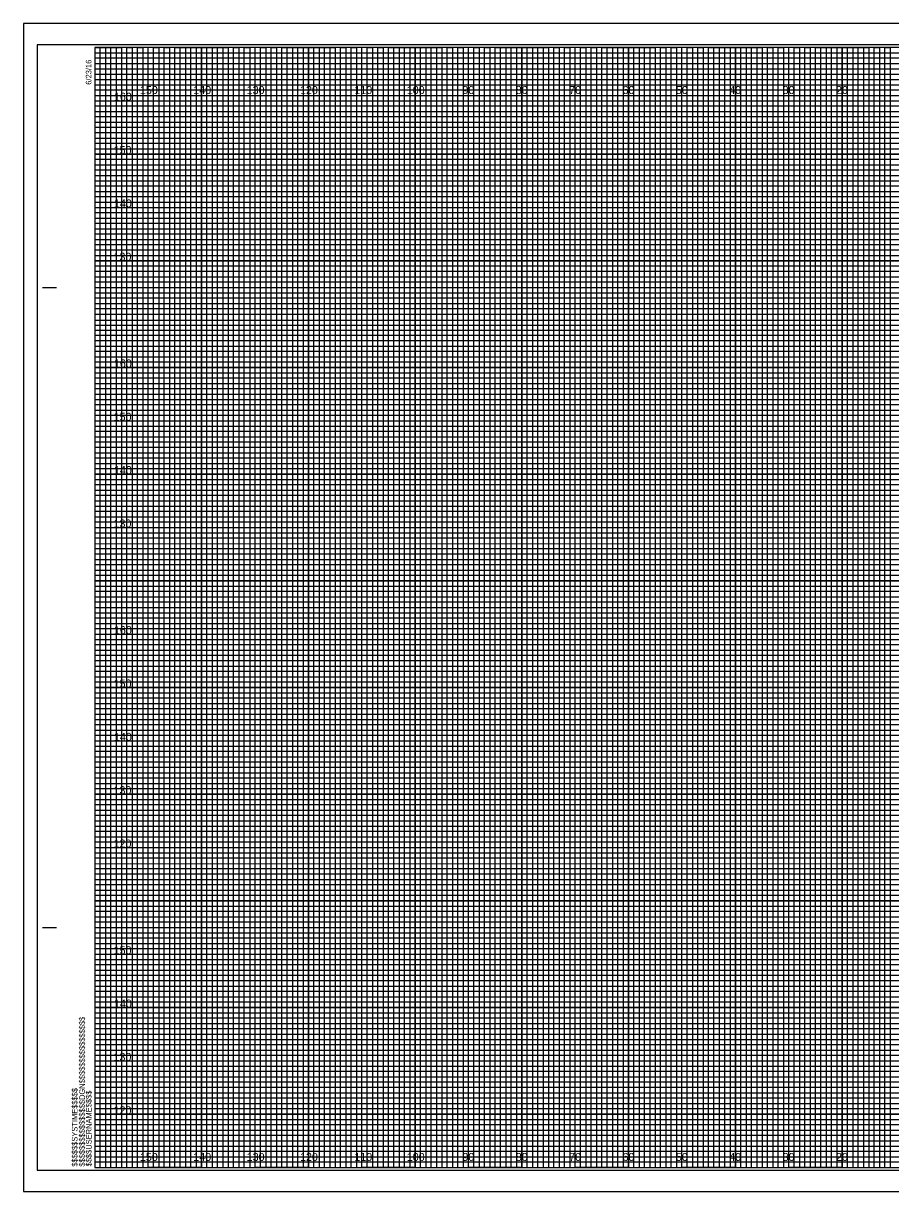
# Model space of a CAD drawing. Extents: x -13 to 323, y -5 to 874.
# Drawn here: x -13.4 to 149.1, y 435.5 to 654.5 of the extents above; entities that cross this region are included whole.
import ezdxf

# ---------------------------------------------------------------- set-up
doc = ezdxf.new("R2010")
doc.units = 0
for name, color, linetype in [('Exist Cross Section Cell', 7, 'Continuous'), ('Exist XS Center Line Elevation Label', 7, 'Continuous'), ('Exist XS Ground Line', 7, 'Continuous'), ('Prop CMT Pvmt Course 1', 7, 'Continuous'), ('Prop CMT Pvmt Course 3', 7, 'Continuous'), ('Prop CMT Pvmt Surface', 7, 'Continuous'), ('Prop CMT Pvmt Surface Shoulder', 7, 'Continuous'), ('Prop CMT Shld Paved Course 1', 7, 'Continuous'), ('Prop CMT Shld Paved Course 2', 7, 'Continuous'), ('Prop CMT Shld Paved Course 3', 7, 'Continuous'), ('Prop CMT Subgrade Earthwork', 7, 'Continuous')]:
    doc.layers.add(name, color=color, linetype=linetype)

msp = doc.modelspace()

# ---------------------------------------------------------------- linework, layer by layer
at = {"layer": 'Exist XS Center Line Elevation Label'}
for points in [[(0, 650), (5, 650), (5, 440), (15, 440), (15, 650), (25, 650), (25, 440), (35, 440), (35, 650), (45, 650), (45, 440), (55, 440), (55, 650), (65, 650), (65, 440), (75, 440), (75, 650), (85, 650), (85, 440), (95, 440), (95, 650), (105, 650), (105, 440), (115, 440), (115, 650), (125, 650), (125, 440), (135, 440), (135, 650), (145, 650), (145, 440), (155, 440)], [(0, 645), (275, 645)], [(0, 625), (320, 625), (320, 635), (0, 635)], [(0, 605), (320, 605), (320, 615), (0, 615)], [(0, 585), (320, 585), (320, 595), (0, 595)], [(0, 565), (320, 565), (320, 575), (0, 575)], [(0, 545), (320, 545), (320, 555), (0, 555)], [(0, 525), (320, 525), (320, 535), (0, 535)], [(0, 505), (320, 505), (320, 515), (0, 515)], [(0, 485), (320, 485), (320, 495), (0, 495)], [(0, 465), (320, 465), (320, 475), (0, 475)], [(0, 445), (320, 445), (320, 455), (0, 455)]]:
    msp.add_lwpolyline(points, dxfattribs=at)
at = {"layer": 'Exist XS Ground Line'}
for p, q in [((10, 650), (0, 650)), ((10, 440), (10, 650)), ((30, 650), (20, 650)), ((20, 650), (20, 440)), ((30, 440), (30, 650)), ((50, 650), (40, 650)), ((40, 650), (40, 440)), ((50, 440), (50, 650)), ((70, 650), (60, 650)), ((60, 650), (60, 440)), ((70, 440), (70, 650)), ((90, 650), (80, 650)), ((80, 650), (80, 440)), ((90, 440), (90, 650)), ((110, 650), (100, 650)), ((100, 650), (100, 440)), ((110, 440), (110, 650)), ((130, 650), (120, 650)), ((120, 650), (120, 440)), ((130, 440), (130, 650)), ((150, 650), (140, 650)), ((140, 650), (140, 440)), ((20, 440), (10, 440)), ((40, 440), (30, 440)), ((60, 440), (50, 440)), ((80, 440), (70, 440)), ((100, 440), (90, 440)), ((120, 440), (110, 440)), ((140, 440), (130, 440))]:
    msp.add_line(p, q, dxfattribs=at)
for points in [[(0, 640), (320, 640), (320, 630), (0, 630)], [(0, 620), (320, 620), (320, 610), (0, 610)], [(0, 600), (320, 600), (320, 590), (0, 590)], [(0, 580), (320, 580), (320, 570), (0, 570)], [(0, 560), (320, 560), (320, 550), (0, 550)], [(0, 540), (320, 540), (320, 530), (0, 530)], [(0, 520), (320, 520), (320, 510), (0, 510)], [(0, 500), (320, 500), (320, 490), (0, 490)], [(0, 480), (320, 480), (320, 470), (0, 470)], [(0, 460), (320, 460), (320, 450), (0, 450)]]:
    msp.add_lwpolyline(points, dxfattribs=at)
at = {"layer": 'Prop CMT Pvmt Course 3'}
msp.add_lwpolyline([(-13.4, 435.5), (323.3, 435.5), (323.3, 654.5), (-13.4, 654.5)], close=True, dxfattribs=at)
at = {"layer": 'Prop CMT Pvmt Surface'}
for p, q in [((10, 440), (10, 650)), ((20, 440), (20, 650)), ((30, 440), (30, 650)), ((40, 440), (40, 650)), ((50, 440), (50, 650)), ((60, 440), (60, 650)), ((70, 440), (70, 650)), ((80, 440), (80, 650)), ((90, 440), (90, 650)), ((100, 440), (100, 650)), ((110, 440), (110, 650)), ((120, 440), (120, 650)), ((130, 440), (130, 650)), ((140, 440), (140, 650)), ((0, 640), (320, 640)), ((0, 630), (320, 630)), ((0, 620), (320, 620)), ((0, 610), (320, 610)), ((0, 600), (320, 600)), ((0, 590), (320, 590)), ((0, 580), (320, 580)), ((0, 570), (320, 570)), ((0, 560), (320, 560)), ((0, 550), (320, 550)), ((0, 540), (320, 540)), ((0, 530), (320, 530)), ((0, 520), (320, 520)), ((0, 510), (320, 510)), ((0, 500), (320, 500)), ((0, 490), (320, 490)), ((0, 480), (320, 480)), ((0, 470), (320, 470)), ((0, 460), (320, 460)), ((0, 450), (320, 450))]:
    msp.add_line(p, q, dxfattribs=at)
at = {"layer": 'Prop CMT Pvmt Surface Shoulder'}
for p, q in [((323.3, 654.5), (-13.4, 654.5)), ((-13.4, 654.5), (-13.4, 435.5)), ((-13.4, 435.5), (323.3, 435.5))]:
    msp.add_line(p, q, dxfattribs=at)
at = {"layer": 'Prop CMT Shld Paved Course 1'}
for p, q in [((0, 649), (260, 649)), ((260, 647.98), (0, 647.98)), ((0, 647.98), (0, 647)), ((0, 647), (260, 647)), ((260, 645.89), (0, 645.89)), ((0, 645.89), (0, 644)), ((0, 644), (320, 644))]:
    msp.add_line(p, q, dxfattribs=at)
for points in [[(0, 643), (270, 643), (320, 643), (320, 642), (0, 642)], [(0, 641), (320, 641), (320, 639), (0, 639)], [(0, 638), (320, 638), (320, 637), (0, 636.98)], [(0, 636), (320, 636), (320, 634), (0, 634)], [(0, 633), (320, 633), (320, 632), (0, 632)], [(0, 631), (320, 631), (320, 629), (0, 629)], [(0, 628), (320, 628), (320, 627), (0, 627)], [(0, 626), (320, 626), (320, 624), (0, 624)], [(0, 623), (320, 623), (320, 622), (0, 622)], [(0, 621), (320, 621), (320, 619), (0, 619)], [(0, 618), (320, 618), (320, 617), (0, 617)], [(0, 616), (320, 616), (320, 613.95), (320, 613), (320, 612), (0, 612)], [(0, 614), (320, 614), (320, 613), (0, 613)], [(0, 611), (320, 611), (320, 609), (0, 609.03)], [(0, 609.03), (320, 609), (320, 608), (0, 608)], [(0, 607), (320, 607), (320, 606), (0, 606)], [(0, 604), (320, 604), (320, 603), (0, 603)], [(0, 602), (320, 602), (320, 601), (0, 601)], [(-0.07, 598.89), (320, 598.89), (320, 597.88), (-0.07, 597.88)], [(0, 597), (320, 597), (320, 596), (0, 596)], [(0, 594), (320, 594), (320, 593), (0, 593)], [(0, 592), (320, 592), (320, 591), (0, 591)], [(0, 589), (320, 589), (320, 588), (0, 588)], [(0, 587), (320, 587), (320, 586), (0, 586)], [(0, 584), (320, 584), (320, 583), (0, 583)], [(0, 582), (320, 582), (320, 581), (0, 581)], [(0, 579), (320, 579), (319.99, 577.98), (0, 578)], [(0, 577), (320, 577), (320, 576), (0, 576)], [(0, 574), (320, 574), (320, 573), (0, 573)], [(0, 572), (320, 572), (320, 571), (0, 571)], [(0, 569), (320, 569), (320, 568), (0, 568)], [(0, 567), (320, 567), (320, 566), (0, 566)], [(0, 564), (320, 564), (320, 563), (0, 563)], [(0, 562), (320, 562), (320, 561), (0, 561)], [(0, 559), (320, 559), (320, 558), (0, 558)], [(0, 556.99), (320.07, 556.91), (320, 556), (0, 556)], [(0, 554), (320, 554), (320, 553), (0, 553)], [(0, 552), (320, 552), (320, 551), (0, 551)], [(0, 549), (320, 549), (320, 548), (0, 548)], [(0, 547), (320, 547), (320, 546), (0, 546)], [(0, 544), (320, 544), (320, 543), (0, 543)], [(0, 542), (320, 542), (320, 541), (0, 541)], [(0, 539), (320, 539), (320, 538), (0, 538)], [(0, 537), (320, 537), (320, 536), (0, 536)], [(0, 534), (320, 534), (320, 533), (0, 533)], [(0, 532), (320, 532), (320, 531), (0, 531)], [(0, 529), (320, 529), (320, 528), (0, 528)], [(0, 527), (320, 527), (320, 526), (0, 526)], [(0, 524), (320, 524), (320, 523), (0, 523)], [(0, 522), (320, 522), (320, 521), (0, 521)], [(0, 519), (320, 519), (319.99, 517.98), (0, 518)], [(0, 517), (320, 517), (320, 516), (0, 516)], [(0, 514), (320, 514), (320, 513), (0, 513)], [(0, 512), (320, 512), (320, 511), (0, 511)], [(0, 509), (320, 509), (320, 508), (0, 508)], [(0, 507), (320, 507), (320, 506), (0, 506)], [(0, 504), (320, 504), (320, 503), (0, 503)], [(0, 502), (320, 502), (320, 501), (0, 501)], [(0, 499), (320, 499), (320, 498), (0, 498)], [(0, 496.99), (320.07, 496.91), (320, 496), (0, 496)], [(0, 494), (320, 494), (320, 493), (0, 493)], [(0, 492), (320, 492), (320, 491), (0, 491)], [(0, 489), (320, 489), (320, 488), (0, 488)], [(0, 487), (320, 487), (320, 486), (0, 486)], [(0, 484), (320, 484), (320, 483), (0, 483)], [(0, 482), (320, 482), (320, 481), (0, 481)], [(0, 479), (320, 479), (320, 478), (0, 478)], [(0, 477), (320, 477), (320, 476), (0, 476)], [(0, 474), (320, 474), (320, 473), (0, 473)], [(0, 472), (320, 472), (320, 471), (0, 471)], [(0, 469), (320, 469), (320, 468), (0, 468)], [(0, 467), (320, 467), (320, 466), (0, 466)], [(0, 464), (320, 464), (320, 463), (0, 463)], [(0, 462), (320, 462), (320, 461), (0, 461)], [(0, 459), (320, 459), (320, 458), (0, 458)], [(0, 457), (320, 457), (320, 456), (0, 456)], [(0, 454), (320, 454), (320, 453), (0, 453)], [(0, 452), (320, 452), (320, 451), (0, 451)], [(0, 449), (320, 449), (320, 448), (0, 448)], [(0, 447), (320, 447), (320, 446), (0, 446)], [(0, 444), (320, 444), (320, 443), (0, 443)], [(0, 442), (320, 442), (320, 441), (0, 441)]]:
    msp.add_lwpolyline(points, dxfattribs=at)
at = {"layer": 'Prop CMT Shld Paved Course 2'}
for p, q in [((-9.8, 605), (-7.3, 605)), ((-9.7, 605), (-7.2, 605)), ((-9.8, 485), (-7.3, 485)), ((-9.7, 485), (-7.2, 485)), ((0, 440), (0, 440)), ((0, 440), (0, 440)), ((0, 440), (0, 440)), ((0, 440), (0, 440)), ((0, 440), (0, 440)), ((0, 440), (0, 440)), ((0, 440), (0, 440))]:
    msp.add_line(p, q, dxfattribs=at)
msp.add_lwpolyline([(320, 650), (0, 650), (0, 440), (320, 440)], close=True, dxfattribs=at)
at = {"layer": 'Prop CMT Shld Paved Course 3'}
for points in [[(0, 440), (1, 440), (1, 650), (2, 650), (2, 440)], [(2, 440), (3, 440), (3, 650), (4, 650), (4, 440)], [(5, 440), (6, 440), (6, 650), (7, 650), (7, 440)], [(7, 440), (8, 440), (8, 650), (9, 650), (9, 440)], [(10, 440), (11, 440), (11, 650), (12, 650), (12, 440)], [(12, 440), (13, 440), (13, 650), (14, 650), (14, 440)], [(15, 440), (16, 440), (16, 650), (17, 650), (17, 440)], [(17, 440), (18, 440), (18, 650), (19, 650), (19, 440)], [(20, 440), (21, 440), (21, 650), (22, 650), (22, 440)], [(22, 440), (23, 440), (23, 650), (24, 650), (24, 440)], [(25, 440), (26, 440), (26, 650), (27, 650), (27, 440)], [(27, 440), (28, 440), (28, 650), (29, 650), (29, 440)], [(30, 440), (31, 440), (31, 650), (32, 650), (32, 440)], [(32, 440), (33, 440), (33, 650), (34, 650), (34, 440)], [(35, 440), (36, 440), (36, 650), (37, 650), (37, 440)], [(37, 440), (38, 440), (38, 650), (39, 650), (39, 440)], [(40, 440), (41, 440), (41, 650), (42, 650), (42, 440)], [(42, 440), (43, 440), (43, 650), (44, 650), (44, 440)], [(45, 440), (46, 440), (46, 650), (47, 650), (47, 440)], [(47, 440), (48, 440), (48, 650), (49, 650), (49, 440)], [(50, 440), (51, 440), (51, 650), (52, 650), (52, 440)], [(52, 440), (53, 440), (53, 650), (54, 650), (54, 440)], [(55, 440), (56, 440), (56, 650), (57, 650), (57, 440)], [(57, 440), (58, 440), (58, 650), (59, 650), (59, 440)], [(60, 440), (61, 440), (61, 650), (62, 650), (62, 440)], [(62, 440), (63, 440), (63, 650), (64, 650), (64, 440)], [(65, 440), (66, 440), (66, 650), (67, 650), (67, 440)], [(67, 440), (68, 440), (68, 650), (69, 650), (69, 440)], [(70, 440), (71, 440), (71, 650), (72, 650), (72, 440)], [(72, 440), (73, 440), (73, 650), (74, 650), (74, 440)], [(75, 440), (76, 440), (76, 650), (77, 650), (77, 440)], [(77, 440), (78, 440), (78, 650), (79, 650), (79, 440)], [(80, 440), (81, 440), (81, 650), (82, 650), (82, 440)], [(82, 440), (83, 440), (83, 650), (84, 650), (84, 440)], [(85, 440), (86, 440), (86, 650), (87, 650), (87, 440)], [(87, 440), (88, 440), (88, 650), (89, 650), (89, 440)], [(90, 440), (91, 440), (91, 650), (92, 650), (92, 440)], [(92, 440), (93, 440), (93, 650), (94, 650), (94, 440)], [(95, 440), (96, 440), (96, 650), (97, 650), (97, 440)], [(97, 440), (98, 440), (98, 650), (99, 650), (99, 440)], [(100, 440), (101, 440), (101, 650), (102, 650), (102, 440)], [(102, 440), (103, 440), (103, 650), (104, 650), (104, 440)], [(105, 440), (106, 440), (106, 650), (107, 650), (107, 440)], [(107, 440), (108, 440), (108, 650), (109, 650), (109, 440)], [(110, 440), (111, 440), (111, 650), (112, 650), (112, 440)], [(112, 440), (113, 440), (113, 650), (114, 650), (114, 440)], [(115, 440), (116, 440), (116, 650), (117, 650), (117, 440)], [(117, 440), (118, 440), (118, 650), (119, 650), (119, 440)], [(120, 440), (121, 440), (121, 650), (122, 650), (122, 440)], [(122, 440), (123, 440), (123, 650), (124, 650), (124, 440)], [(125, 440), (126, 440), (126, 650), (127, 650), (127, 440)], [(127, 440), (128, 440), (128, 650), (129, 650), (129, 440)], [(130, 440), (131, 440), (131, 650), (132, 650), (132, 440)], [(132, 440), (133, 440), (133, 650), (134, 650), (134, 440)], [(135, 440), (136, 440), (136, 650), (137, 650), (137, 440)], [(137, 440), (138, 440), (138, 650), (139, 650), (139, 440)], [(140, 440), (141, 440), (141, 650), (142, 650), (142, 440)], [(142, 440), (143, 440), (143, 650), (144, 650), (144, 440)], [(145, 440), (146, 440), (146, 650), (147, 650), (147, 440)], [(147, 440), (148, 440), (148, 650), (149, 650), (149, 440)]]:
    msp.add_lwpolyline(points, dxfattribs=at)
at = {"layer": 'Prop CMT Subgrade Earthwork'}
msp.add_lwpolyline([(-10.8, 439.5), (322.4, 439.5), (322.4, 650.5), (-10.8, 650.5)], close=True, dxfattribs=at)

# ---------------------------------------------------------------- texts
at = {"layer": 'Exist Cross Section Cell'}
for s, p in [('150', (8.44, 641.25)), ('140', (18.44, 641.25)), ('130', (28.44, 641.25)), ('120', (38.44, 641.25)), ('110', (48.62, 641.25)), ('100', (58.44, 641.25)), ('90', (68.86, 641.25)), ('80', (78.86, 641.25)), ('70', (88.86, 641.25)), ('60', (98.86, 641.25)), ('50', (108.86, 641.25)), ('40', (118.86, 641.25)), ('30', (128.86, 641.25)), ('20', (138.86, 641.25)), ('150', (8.44, 441.25)), ('140', (18.44, 441.25)), ('130', (28.44, 441.25)), ('120', (38.44, 441.25)), ('110', (48.62, 441.25)), ('100', (58.44, 441.25)), ('90', (68.86, 441.25)), ('80', (78.86, 441.25)), ('70', (88.86, 441.25)), ('60', (98.86, 441.25)), ('50', (108.86, 441.25)), ('40', (118.86, 441.25)), ('30', (128.86, 441.25)), ('20', (138.86, 441.25))]:
    msp.add_text(s, height=1.5, dxfattribs=at).set_placement(p)
at = {"layer": 'Prop CMT Pvmt Course 1'}
for s, p in [('160', (3.57, 640)), ('150', (3.52, 630)), ('140', (3.57, 620)), ('130', (3.49, 610)), ('160', (3.57, 590)), ('150', (3.52, 580)), ('140', (3.57, 570)), ('130', (3.49, 560)), ('160', (3.57, 540)), ('150', (3.52, 530)), ('140', (3.57, 520)), ('130', (3.49, 510)), ('120', (3.5, 500)), ('150', (3.52, 480)), ('140', (3.57, 470)), ('130', (3.49, 460)), ('120', (3.5, 450))]:
    msp.add_text(s, height=1.5, dxfattribs=at).set_placement(p)
at = {"layer": 'Prop CMT Shld Paved Course 2'}
for s, p in [('6/23/16', (-0.65, 643)), ('$$$$$$$$$$$$$$$$DGN$$$$$$$$$$$$$$$$', (-1.88, 440.18)), ('$$$$$$SYSTIME$$$$$', (-3.26, 440.18)), ('$$$$USERNAME$$$$', (-0.62, 440.23))]:
    msp.add_text(s, height=1.05, rotation=90, dxfattribs=at).set_placement(p)

doc.saveas('drawing.dxf')
